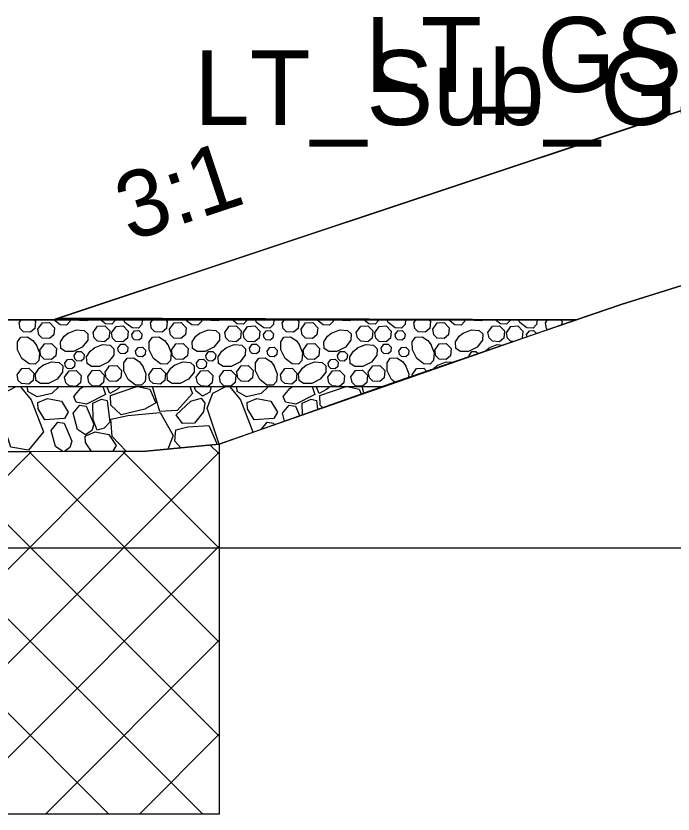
# Model space of a CAD drawing. Extents: x -14026 to 1303, y -10 to 9533.
# Drawn here: x 119.15 to 129.03, y 3996 to 4007.99 of the extents above; entities that cross this region are included whole.
import ezdxf

# ---------------------------------------------------------------- set-up
doc = ezdxf.new("R2010")
doc.units = 0
for name, color, linetype in [('Exist Cross Section Cell', 7, 'Continuous'), ('Exist XS Ground Line', 7, 'Continuous'), ('Old_Level_10', 7, 'Continuous'), ('Prop CMT Slope Grass', 7, 'Continuous'), ('Prop CMT Subgrade Earthwork', 7, 'Continuous'), ('Prop XS Earthwork Shape', 7, 'Continuous'), ('Prop XS Side Slope Text', 7, 'Continuous'), ('Scratch_Level_0', 7, 'Continuous'), ('Scratch_Level_3', 7, 'Continuous'), ('Scratch_Level_5', 7, 'Continuous')]:
    doc.layers.add(name, color=color, linetype=linetype)

msp = doc.modelspace()

# ---------------------------------------------------------------- linework, layer by layer
at = {"layer": 'Exist Cross Section Cell'}
msp.add_line((0, 4000), (150, 4000), dxfattribs=at)
at = {"layer": 'Exist XS Ground Line'}
msp.add_lwpolyline([(103.803, 4001.139), (113.961, 4001.433), (121.109, 4001.453), (122.206, 4001.557), (124.865, 4002.502), (128.249, 4003.656), (131.147, 4004.565), (132.692, 4005.022), (133.861, 4005.345), (137.453, 4006.434), (141.559, 4006.646), (143.818, 4006.925), (150, 4006.975), (154.881, 4007.014), (166.19, 4007.028)], dxfattribs=at)
at = {"layer": 'Old_Level_10'}
for p, q in [((119.196, 4003.38), (119.228, 4003.426)), ((121.174, 4003.38), (121.207, 4003.426)), ((123.153, 4003.38), (123.185, 4003.426)), ((125.132, 4003.38), (125.164, 4003.426)), ((127.11, 4003.38), (127.143, 4003.426)), ((126.834, 4003.173), (126.828, 4003.204)), ((126.204, 4002.957), (126.266, 4003.007)), ((125.965, 4002.875), (125.962, 4002.891)), ((125.108, 4002.583), (125.105, 4002.6)), ((115.211, 4002.426), (124.649, 4002.426)), ((124.38, 4002.33), (124.353, 4002.426))]:
    msp.add_line(p, q, dxfattribs=at)
msp.add_lwpolyline([(121.109, 4001.453), (113.711, 4001.425), (116.711, 4003.426), (127.573, 4003.426), (122.206, 4001.557)], close=True, dxfattribs=at)
for points in [[(119.424, 4003.426), (119.445, 4003.404), (119.434, 4003.296), (119.368, 4003.24), (119.262, 4003.248), (119.212, 4003.296), (119.196, 4003.38)], [(119.962, 4003.426), (119.96, 4003.403), (119.908, 4003.348), (119.814, 4003.35), (119.717, 4003.426)], [(120.232, 4003.426), (120.213, 4003.41), (120.107, 4003.417), (120.099, 4003.426)], [(120.644, 4003.426), (120.643, 4003.419), (120.591, 4003.364), (120.497, 4003.366), (120.421, 4003.426)], [(121.048, 4003.426), (121.042, 4003.358), (120.99, 4003.303), (120.896, 4003.305), (120.789, 4003.388), (120.771, 4003.426)], [(121.403, 4003.426), (121.423, 4003.404), (121.413, 4003.296), (121.346, 4003.24), (121.24, 4003.248), (121.19, 4003.296), (121.174, 4003.38)], [(121.941, 4003.426), (121.939, 4003.403), (121.886, 4003.348), (121.793, 4003.35), (121.696, 4003.426)], [(122.211, 4003.426), (122.192, 4003.41), (122.086, 4003.417), (122.077, 4003.426)], [(122.622, 4003.426), (122.622, 4003.419), (122.57, 4003.364), (122.476, 4003.366), (122.4, 4003.426)], [(123.026, 4003.426), (123.02, 4003.358), (122.968, 4003.303), (122.875, 4003.305), (122.768, 4003.388), (122.749, 4003.426)], [(123.381, 4003.426), (123.402, 4003.404), (123.391, 4003.296), (123.325, 4003.24), (123.219, 4003.248), (123.169, 4003.296), (123.153, 4003.38)], [(123.919, 4003.426), (123.917, 4003.403), (123.865, 4003.348), (123.771, 4003.35), (123.674, 4003.426)], [(124.189, 4003.426), (124.17, 4003.41), (124.064, 4003.417), (124.056, 4003.426)], [(124.601, 4003.426), (124.601, 4003.419), (124.548, 4003.364), (124.455, 4003.366), (124.378, 4003.426)], [(125.005, 4003.426), (124.999, 4003.358), (124.947, 4003.303), (124.853, 4003.305), (124.747, 4003.388), (124.728, 4003.426)], [(125.36, 4003.426), (125.381, 4003.404), (125.37, 4003.296), (125.304, 4003.24), (125.198, 4003.248), (125.148, 4003.296), (125.132, 4003.38)], [(125.898, 4003.426), (125.896, 4003.403), (125.844, 4003.348), (125.75, 4003.35), (125.653, 4003.426)], [(126.168, 4003.426), (126.149, 4003.41), (126.043, 4003.417), (126.035, 4003.426)], [(126.58, 4003.426), (126.579, 4003.419), (126.527, 4003.364), (126.433, 4003.366), (126.357, 4003.426)], [(126.984, 4003.426), (126.978, 4003.358), (126.926, 4003.303), (126.832, 4003.305), (126.725, 4003.388), (126.707, 4003.426)], [(127.339, 4003.426), (127.36, 4003.404), (127.354, 4003.351)], [(119.48, 4003.285), (119.547, 4003.38), (119.654, 4003.386), (119.729, 4003.309), (119.718, 4003.201), (119.652, 4003.145), (119.546, 4003.153), (119.496, 4003.201), (119.48, 4003.285)], [(120.31, 4003.237), (120.377, 4003.333), (120.484, 4003.339), (120.559, 4003.262), (120.548, 4003.153), (120.482, 4003.098), (120.376, 4003.106), (120.326, 4003.154), (120.31, 4003.237)], [(120.586, 4003.233), (120.654, 4003.329), (120.761, 4003.335), (120.836, 4003.258), (120.825, 4003.149), (120.759, 4003.094), (120.653, 4003.102), (120.603, 4003.15), (120.586, 4003.233)], [(121.458, 4003.285), (121.526, 4003.38), (121.633, 4003.386), (121.707, 4003.309), (121.697, 4003.201), (121.63, 4003.145), (121.524, 4003.153), (121.475, 4003.201), (121.458, 4003.285)], [(122.289, 4003.237), (122.356, 4003.333), (122.463, 4003.339), (122.538, 4003.262), (122.527, 4003.153), (122.461, 4003.098), (122.355, 4003.106), (122.305, 4003.154), (122.289, 4003.237)], [(122.565, 4003.233), (122.632, 4003.329), (122.74, 4003.335), (122.814, 4003.258), (122.804, 4003.149), (122.737, 4003.094), (122.631, 4003.102), (122.581, 4003.15), (122.565, 4003.233)], [(123.437, 4003.285), (123.504, 4003.38), (123.612, 4003.386), (123.686, 4003.309), (123.675, 4003.201), (123.609, 4003.145), (123.503, 4003.153), (123.453, 4003.201), (123.437, 4003.285)], [(124.267, 4003.237), (124.335, 4003.333), (124.442, 4003.339), (124.516, 4003.262), (124.506, 4003.153), (124.439, 4003.098), (124.333, 4003.106), (124.284, 4003.154), (124.267, 4003.237)], [(124.544, 4003.233), (124.611, 4003.329), (124.718, 4003.335), (124.793, 4003.258), (124.782, 4003.149), (124.716, 4003.094), (124.61, 4003.102), (124.56, 4003.15), (124.544, 4003.233)], [(125.416, 4003.285), (125.483, 4003.38), (125.59, 4003.386), (125.665, 4003.309), (125.654, 4003.201), (125.588, 4003.145), (125.482, 4003.153), (125.432, 4003.201), (125.416, 4003.285)], [(126.246, 4003.237), (126.313, 4003.333), (126.421, 4003.339), (126.495, 4003.262), (126.484, 4003.153), (126.418, 4003.098), (126.312, 4003.106), (126.262, 4003.154), (126.246, 4003.237)], [(126.523, 4003.233), (126.59, 4003.329), (126.697, 4003.335), (126.772, 4003.258), (126.761, 4003.149), (126.758, 4003.147)], [(127.145, 4003.279), (127.127, 4003.296), (127.11, 4003.38)], [(119.452, 4003.058), (119.502, 4002.933), (119.492, 4002.817), (119.44, 4002.762), (119.346, 4002.764), (119.24, 4002.847), (119.175, 4002.976), (119.173, 4003.097), (119.222, 4003.166), (119.318, 4003.172), (119.405, 4003.117), (119.456, 4003.053)], [(119.935, 4003.228), (120.061, 4003.278), (120.176, 4003.268), (120.231, 4003.216), (120.229, 4003.122), (120.146, 4003.016), (120.017, 4002.951), (119.896, 4002.949), (119.827, 4002.998), (119.821, 4003.095), (119.876, 4003.181), (119.94, 4003.232)], [(120.892, 4003.204), (120.933, 4003.261), (120.997, 4003.265), (121.042, 4003.218), (121.035, 4003.153), (120.996, 4003.12), (120.932, 4003.125), (120.902, 4003.154), (120.892, 4003.204)], [(121.431, 4003.058), (121.481, 4002.933), (121.471, 4002.817), (121.419, 4002.762), (121.325, 4002.764), (121.218, 4002.847), (121.154, 4002.976), (121.152, 4003.097), (121.201, 4003.166), (121.297, 4003.172), (121.384, 4003.117), (121.434, 4003.053)], [(121.914, 4003.228), (122.039, 4003.278), (122.155, 4003.268), (122.21, 4003.216), (122.208, 4003.122), (122.125, 4003.016), (121.996, 4002.951), (121.875, 4002.949), (121.806, 4002.998), (121.8, 4003.095), (121.855, 4003.181), (121.919, 4003.232)], [(122.871, 4003.204), (122.911, 4003.261), (122.976, 4003.265), (123.021, 4003.218), (123.014, 4003.153), (122.974, 4003.12), (122.911, 4003.125), (122.881, 4003.154), (122.871, 4003.204)], [(123.41, 4003.058), (123.46, 4002.933), (123.45, 4002.817), (123.397, 4002.762), (123.304, 4002.764), (123.197, 4002.847), (123.133, 4002.976), (123.131, 4003.097), (123.179, 4003.166), (123.276, 4003.172), (123.362, 4003.117), (123.413, 4003.053)], [(123.892, 4003.228), (124.018, 4003.278), (124.134, 4003.268), (124.189, 4003.216), (124.187, 4003.122), (124.103, 4003.016), (123.975, 4002.951), (123.853, 4002.949), (123.785, 4002.998), (123.778, 4003.095), (123.834, 4003.181), (123.897, 4003.232)], [(124.85, 4003.204), (124.89, 4003.261), (124.954, 4003.265), (124.999, 4003.218), (124.993, 4003.153), (124.953, 4003.12), (124.889, 4003.125), (124.859, 4003.154), (124.85, 4003.204)], [(125.388, 4003.058), (125.438, 4002.933), (125.428, 4002.817), (125.376, 4002.762), (125.282, 4002.764), (125.176, 4002.847), (125.112, 4002.976), (125.109, 4003.097), (125.158, 4003.166), (125.255, 4003.172), (125.341, 4003.117), (125.392, 4003.053)], [(125.871, 4003.228), (125.997, 4003.278), (126.112, 4003.268), (126.167, 4003.216), (126.165, 4003.122), (126.082, 4003.016), (125.953, 4002.951), (125.832, 4002.949), (125.764, 4002.998), (125.757, 4003.095), (125.813, 4003.181), (125.876, 4003.232)], [(126.62, 4003.099), (126.589, 4003.102), (126.539, 4003.15), (126.523, 4003.233)], [(126.828, 4003.204), (126.869, 4003.261), (126.933, 4003.265), (126.975, 4003.221)], [(119.509, 4002.97), (119.577, 4003.066), (119.684, 4003.072), (119.759, 4002.994), (119.748, 4002.886), (119.682, 4002.831), (119.576, 4002.838), (119.526, 4002.887), (119.51, 4002.97)], [(120.325, 4003.004), (120.451, 4003.054), (120.566, 4003.044), (120.621, 4002.991), (120.62, 4002.898), (120.536, 4002.791), (120.407, 4002.727), (120.286, 4002.725), (120.218, 4002.773), (120.211, 4002.87), (120.267, 4002.956), (120.33, 4003.007)], [(120.684, 4003.002), (120.725, 4003.059), (120.789, 4003.063), (120.834, 4003.016), (120.827, 4002.951), (120.788, 4002.918), (120.724, 4002.923), (120.694, 4002.952), (120.684, 4003.002)], [(121.488, 4002.97), (121.555, 4003.066), (121.663, 4003.072), (121.737, 4002.994), (121.727, 4002.886), (121.66, 4002.831), (121.554, 4002.838), (121.504, 4002.887), (121.488, 4002.97)], [(122.304, 4003.004), (122.43, 4003.054), (122.545, 4003.044), (122.6, 4002.991), (122.598, 4002.898), (122.515, 4002.791), (122.386, 4002.727), (122.265, 4002.725), (122.196, 4002.773), (122.19, 4002.87), (122.245, 4002.956), (122.309, 4003.007)], [(122.663, 4003.002), (122.703, 4003.059), (122.768, 4003.063), (122.812, 4003.016), (122.806, 4002.951), (122.766, 4002.918), (122.703, 4002.923), (122.673, 4002.952), (122.663, 4003.002)], [(123.467, 4002.97), (123.534, 4003.066), (123.641, 4003.072), (123.716, 4002.994), (123.705, 4002.886), (123.639, 4002.831), (123.533, 4002.838), (123.483, 4002.887), (123.467, 4002.97)], [(124.282, 4003.004), (124.408, 4003.054), (124.524, 4003.044), (124.579, 4002.991), (124.577, 4002.898), (124.494, 4002.791), (124.365, 4002.727), (124.243, 4002.725), (124.175, 4002.773), (124.169, 4002.87), (124.224, 4002.956), (124.288, 4003.007)], [(124.642, 4003.002), (124.682, 4003.059), (124.746, 4003.063), (124.791, 4003.016), (124.785, 4002.951), (124.745, 4002.918), (124.681, 4002.923), (124.651, 4002.952), (124.642, 4003.002)], [(125.446, 4002.97), (125.513, 4003.066), (125.62, 4003.072), (125.695, 4002.994), (125.684, 4002.886), (125.618, 4002.831), (125.512, 4002.838), (125.462, 4002.887), (125.446, 4002.97)], [(126.261, 4003.004), (126.387, 4003.054), (126.466, 4003.047)], [(120.025, 4002.891), (120.066, 4002.949), (120.13, 4002.953), (120.175, 4002.906), (120.168, 4002.841), (120.129, 4002.808), (120.065, 4002.813), (120.035, 4002.842), (120.025, 4002.891)], [(120.949, 4002.955), (120.989, 4003.012), (121.054, 4003.016), (121.099, 4002.969), (121.092, 4002.904), (121.052, 4002.871), (120.989, 4002.876), (120.959, 4002.905), (120.949, 4002.955)], [(122.004, 4002.891), (122.044, 4002.949), (122.109, 4002.953), (122.154, 4002.906), (122.147, 4002.841), (122.107, 4002.808), (122.044, 4002.813), (122.014, 4002.842), (122.004, 4002.891)], [(122.928, 4002.955), (122.968, 4003.012), (123.033, 4003.016), (123.077, 4002.969), (123.071, 4002.904), (123.031, 4002.871), (122.967, 4002.876), (122.938, 4002.905), (122.928, 4002.955)], [(123.983, 4002.891), (124.023, 4002.949), (124.088, 4002.953), (124.132, 4002.906), (124.126, 4002.841), (124.086, 4002.808), (124.022, 4002.813), (123.993, 4002.842), (123.983, 4002.891)], [(124.906, 4002.955), (124.947, 4003.012), (125.011, 4003.016), (125.056, 4002.969), (125.05, 4002.904), (125.01, 4002.871), (124.946, 4002.876), (124.916, 4002.905), (124.907, 4002.955)], [(125.962, 4002.891), (126.002, 4002.949), (126.066, 4002.953), (126.097, 4002.921)], [(119.887, 4002.775), (119.927, 4002.832), (119.991, 4002.836), (120.036, 4002.789), (120.03, 4002.724), (119.99, 4002.691), (119.926, 4002.696), (119.896, 4002.725), (119.887, 4002.775)], [(121.051, 4002.741), (121.101, 4002.615), (121.091, 4002.5), (121.038, 4002.445), (120.945, 4002.447), (120.838, 4002.53), (120.774, 4002.659), (120.772, 4002.78), (120.82, 4002.849), (120.917, 4002.855), (121.003, 4002.8), (121.054, 4002.736)], [(121.865, 4002.775), (121.906, 4002.832), (121.97, 4002.836), (122.015, 4002.789), (122.008, 4002.724), (121.969, 4002.691), (121.905, 4002.696), (121.875, 4002.725), (121.865, 4002.775)], [(123.029, 4002.741), (123.079, 4002.615), (123.069, 4002.5), (123.017, 4002.445), (122.923, 4002.447), (122.817, 4002.53), (122.752, 4002.659), (122.75, 4002.78), (122.799, 4002.849), (122.895, 4002.855), (122.982, 4002.8), (123.033, 4002.736)], [(123.844, 4002.775), (123.884, 4002.832), (123.949, 4002.836), (123.994, 4002.789), (123.987, 4002.724), (123.947, 4002.691), (123.884, 4002.696), (123.854, 4002.725), (123.844, 4002.775)], [(124.844, 4002.492), (124.795, 4002.53), (124.731, 4002.659), (124.729, 4002.78), (124.778, 4002.849), (124.874, 4002.855), (124.961, 4002.8), (125.011, 4002.736)], [(119.169, 4002.6), (119.236, 4002.696), (119.343, 4002.702), (119.418, 4002.625), (119.407, 4002.516), (119.341, 4002.461), (119.235, 4002.469), (119.185, 4002.517), (119.169, 4002.6)], [(119.556, 4002.748), (119.682, 4002.797), (119.798, 4002.787), (119.853, 4002.735), (119.851, 4002.642), (119.768, 4002.535), (119.639, 4002.471), (119.517, 4002.468), (119.449, 4002.517), (119.443, 4002.614), (119.498, 4002.7), (119.562, 4002.751)], [(120.49, 4002.639), (120.557, 4002.734), (120.664, 4002.741), (120.739, 4002.663), (120.728, 4002.555), (120.662, 4002.5), (120.556, 4002.507), (120.506, 4002.556), (120.49, 4002.639)], [(121.148, 4002.6), (121.215, 4002.696), (121.322, 4002.702), (121.397, 4002.625), (121.386, 4002.516), (121.32, 4002.461), (121.214, 4002.469), (121.164, 4002.517), (121.148, 4002.6)], [(121.535, 4002.748), (121.661, 4002.797), (121.776, 4002.787), (121.831, 4002.735), (121.83, 4002.642), (121.746, 4002.535), (121.618, 4002.471), (121.496, 4002.468), (121.428, 4002.517), (121.421, 4002.614), (121.477, 4002.7), (121.54, 4002.751)], [(122.468, 4002.639), (122.536, 4002.734), (122.643, 4002.741), (122.718, 4002.663), (122.707, 4002.555), (122.641, 4002.5), (122.535, 4002.507), (122.485, 4002.556), (122.469, 4002.639)], [(123.126, 4002.6), (123.193, 4002.696), (123.301, 4002.702), (123.375, 4002.625), (123.365, 4002.516), (123.298, 4002.461), (123.192, 4002.469), (123.142, 4002.517), (123.126, 4002.6)], [(123.514, 4002.748), (123.64, 4002.797), (123.755, 4002.787), (123.81, 4002.735), (123.808, 4002.642), (123.725, 4002.535), (123.596, 4002.471), (123.475, 4002.468), (123.407, 4002.517), (123.4, 4002.614), (123.456, 4002.7), (123.519, 4002.751)], [(124.447, 4002.639), (124.514, 4002.734), (124.622, 4002.741), (124.696, 4002.663), (124.686, 4002.555), (124.619, 4002.5), (124.513, 4002.507), (124.463, 4002.556), (124.447, 4002.639)], [(125.008, 4002.741), (125.058, 4002.615), (125.053, 4002.564)], [(125.105, 4002.6), (125.172, 4002.696), (125.28, 4002.702), (125.324, 4002.656)], [(125.429, 4002.692), (125.434, 4002.7), (125.498, 4002.751)], [(125.493, 4002.748), (125.618, 4002.797), (125.713, 4002.789)], [(119.882, 4002.565), (119.949, 4002.66), (120.057, 4002.666), (120.131, 4002.589), (120.121, 4002.481), (120.054, 4002.426), (119.948, 4002.433), (119.898, 4002.482), (119.882, 4002.565)], [(120.229, 4002.569), (120.296, 4002.664), (120.404, 4002.67), (120.478, 4002.593), (120.467, 4002.485), (120.401, 4002.429), (120.295, 4002.437), (120.245, 4002.486), (120.229, 4002.569)], [(121.861, 4002.565), (121.928, 4002.66), (122.035, 4002.666), (122.11, 4002.589), (122.099, 4002.481), (122.033, 4002.426), (121.927, 4002.433), (121.877, 4002.482), (121.861, 4002.565)], [(122.208, 4002.569), (122.275, 4002.664), (122.382, 4002.67), (122.457, 4002.593), (122.446, 4002.485), (122.38, 4002.429), (122.274, 4002.437), (122.224, 4002.486), (122.208, 4002.569)], [(123.84, 4002.565), (123.907, 4002.66), (124.014, 4002.666), (124.089, 4002.589), (124.078, 4002.481), (124.012, 4002.426), (123.906, 4002.433), (123.856, 4002.482), (123.84, 4002.565)], [(124.186, 4002.569), (124.254, 4002.664), (124.361, 4002.67), (124.436, 4002.593), (124.425, 4002.485), (124.359, 4002.429), (124.253, 4002.437), (124.203, 4002.486), (124.187, 4002.569)], [(119.217, 4002.419), (119.381, 4002.225), (119.563, 4001.745), (119.336, 4001.467), (119.072, 4001.512), (118.879, 4002.099), (118.964, 4002.327), (119.155, 4002.426)], [(119.799, 4002.426), (119.688, 4002.322), (119.471, 4002.27), (119.33, 4002.351), (119.324, 4002.426)], [(120.021, 4002.273), (120.121, 4002.395), (120.161, 4002.426)], [(120.454, 4002.426), (120.495, 4002.304), (120.208, 4002.162), (120.056, 4002.192), (120.021, 4002.273)], [(120.561, 4002.321), (120.52, 4002.413), (120.514, 4002.426)], [(120.724, 4002.426), (120.671, 4002.382), (120.561, 4002.321)], [(121.251, 4002.182), (121.086, 4002.082), (120.733, 4001.999), (120.577, 4002.143), (120.571, 4002.292), (120.966, 4002.426)], [(120.981, 4002.426), (121.161, 4002.385), (121.251, 4002.182)], [(121.763, 4002.426), (121.803, 4002.319), (121.575, 4002.066), (121.313, 4002.049), (121.205, 4002.426)], [(121.953, 4002.281), (121.856, 4002.358), (121.831, 4002.426)], [(122.087, 4002.426), (122.063, 4002.342), (121.953, 4002.281)], [(122.205, 4001.557), (122.027, 4002.099), (122.111, 4002.327), (122.303, 4002.426)], [(122.364, 4002.419), (122.528, 4002.225), (122.711, 4001.745), (122.701, 4001.733)], [(122.946, 4002.426), (122.835, 4002.322), (122.618, 4002.27), (122.477, 4002.351), (122.471, 4002.426)], [(123.168, 4002.273), (123.269, 4002.395), (123.308, 4002.426)], [(123.602, 4002.426), (123.643, 4002.304), (123.356, 4002.162), (123.204, 4002.192), (123.168, 4002.273)], [(123.709, 4002.321), (123.667, 4002.413), (123.661, 4002.426)], [(123.872, 4002.426), (123.819, 4002.382), (123.709, 4002.321)], [(123.76, 4002.11), (123.724, 4002.143), (123.718, 4002.292), (124.113, 4002.426)], [(124.128, 4002.426), (124.309, 4002.385), (124.34, 4002.315)], [(119.478, 4002.183), (119.625, 4002.246), (119.834, 4002.204), (119.934, 4002.039), (119.882, 4001.943), (119.582, 4001.925), (119.482, 4002.09), (119.478, 4002.183)], [(120.371, 4001.768), (120.31, 4001.922), (120.304, 4002.177), (120.438, 4002.236), (120.522, 4002.213), (120.561, 4001.89), (120.476, 4001.797), (120.371, 4001.768)], [(121.99, 4002.176), (121.967, 4002.045), (121.833, 4001.876), (121.656, 4001.868), (121.559, 4001.998), (121.78, 4002.205), (121.932, 4002.249), (121.99, 4002.176)], [(122.625, 4002.183), (122.773, 4002.246), (122.981, 4002.204), (123.082, 4002.039), (123.029, 4001.943), (122.73, 4001.925), (122.629, 4002.09), (122.625, 4002.183)], [(123.456, 4002.001), (123.452, 4002.177), (123.586, 4002.236), (123.67, 4002.213), (123.685, 4002.083)], [(120.197, 4001.698), (120.075, 4001.781), (120.009, 4002.022), (120.11, 4002.145), (120.205, 4002.13), (120.322, 4001.86), (120.289, 4001.765), (120.197, 4001.698)], [(123.188, 4001.906), (123.157, 4002.022), (123.258, 4002.145), (123.352, 4002.13), (123.415, 4001.987)], [(120.578, 4001.935), (120.832, 4001.989), (121.318, 4002.034), (121.513, 4001.691), (121.433, 4001.484)], [(119.855, 4001.448), (119.745, 4001.523), (119.679, 4001.764), (119.781, 4001.887), (119.875, 4001.872), (119.992, 4001.602), (119.959, 4001.506), (119.879, 4001.448)], [(120.809, 4001.452), (120.595, 4001.673), (120.578, 4001.935)], [(122.843, 4001.784), (122.928, 4001.887), (123.023, 4001.872), (123.032, 4001.851)], [(120.192, 4001.677), (120.339, 4001.746), (120.547, 4001.704), (120.654, 4001.54), (120.606, 4001.451)], [(121.628, 4001.502), (121.54, 4001.605), (121.552, 4001.774)], [(121.552, 4001.774), (121.732, 4001.819), (122.05, 4001.838), (122.167, 4001.58), (122.161, 4001.553)], [(120.286, 4001.45), (120.196, 4001.584), (120.192, 4001.677)]]:
    msp.add_lwpolyline(points, dxfattribs=at)
at = {"layer": 'Prop CMT Slope Grass'}
msp.add_line((119.789, 4003.452), (127.573, 4003.426), dxfattribs=at)
msp.add_lwpolyline([(130, 4006.852), (119.789, 4003.452)], dxfattribs=at)
at = {"layer": 'Prop CMT Subgrade Earthwork'}
msp.add_line((119.711, 4003.426), (127.573, 4003.426), dxfattribs=at)
for points in [[(130, 4006.852), (128.506, 4006.354)], [(128.506, 4006.354), (119.711, 4003.426)]]:
    msp.add_lwpolyline(points, dxfattribs=at)
at = {"layer": 'Prop XS Earthwork Shape'}
msp.add_lwpolyline([(166.19, 4007.028), (154.881, 4007.014), (150, 4006.975), (143.818, 4006.925), (141.559, 4006.646), (137.453, 4006.434), (133.861, 4005.345), (132.692, 4005.022), (131.147, 4004.565), (128.249, 4003.656), (127.573, 4003.426), (119.789, 4003.452), (130, 4006.852), (136, 4007.332), (138, 4007.382), (141.559, 4007.471), (150, 4007.682), (162, 4007.382)], dxfattribs=at)
msp.add_lwpolyline([(141.559, 4006.681), (141.559, 4006.646), (137.453, 4006.434), (133.861, 4005.345), (132.692, 4005.022), (131.147, 4004.565), (128.249, 4003.656), (127.573, 4003.426), (119.711, 4003.426), (128.506, 4006.354), (130, 4006.852), (134.5, 4007.212), (135.19, 4006.521), (138, 4006.592)], close=True, dxfattribs=at)
at = {"layer": 'Scratch_Level_3'}
msp.add_line((127.573, 4003.426), (109.446, 4003.426), dxfattribs=at)
at = {"layer": 'Scratch_Level_5'}
for p, q in [((122.072, 4001.544), (122.206, 4001.411)), ((113.937, 3996), (119.383, 4001.447)), ((115.114, 4001.431), (120.545, 3996)), ((115.351, 3996), (120.803, 4001.452)), ((116.523, 4001.436), (121.959, 3996)), ((116.765, 3996), (122.206, 4001.44)), ((117.932, 4001.441), (122.206, 3997.168)), ((119.341, 4001.446), (122.206, 3998.582)), ((120.75, 4001.452), (122.206, 3999.996)), ((118.179, 3996), (122.206, 4000.026)), ((119.594, 3996), (122.206, 3998.612)), ((121.008, 3996), (122.206, 3997.198))]:
    msp.add_line(p, q, dxfattribs=at)
msp.add_lwpolyline([(122.206, 4001.557), (122.206, 3996), (113.705, 3996), (113.705, 4001.426), (113.961, 4001.433), (121.109, 4001.453)], close=True, dxfattribs=at)

# ---------------------------------------------------------------- texts
at = {"layer": 'Prop XS Side Slope Text'}
msp.add_text('3:1', height=1, rotation=18.4178, dxfattribs=at).set_placement((120.864, 4004.6))
at = {"layer": 'Scratch_Level_0'}
for s, p in [('LT_GS_OS_CTL', (124.4, 4006.852)), ('LT_Sub_Graded_Tie', (121.827, 4006.354))]:
    msp.add_text(s, height=1.125, dxfattribs=at).set_placement(p)

doc.saveas('drawing.dxf')
